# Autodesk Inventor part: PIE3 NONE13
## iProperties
Shininess: 64.0
Length Units: 11269
Angle Units: 11279
Time Units: 11290
Mass Units: 11286
Length Display Precision: 3
Angle Display Precision: 2
Compacted: True
Part Number: PIE3 NONE13
Document SubType Name: Modeling
Created: 2004-08
Designer: John Blackburn
Manufacturer: Standard
Standards Organization: Custom
Density: 0.0
Volumn: 0.0
Area: 0.0
PropertySet Name: Model Information
Control State: 0
Master: False
Checked Out: False
Author: John Blackburn
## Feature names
1. Erst1
